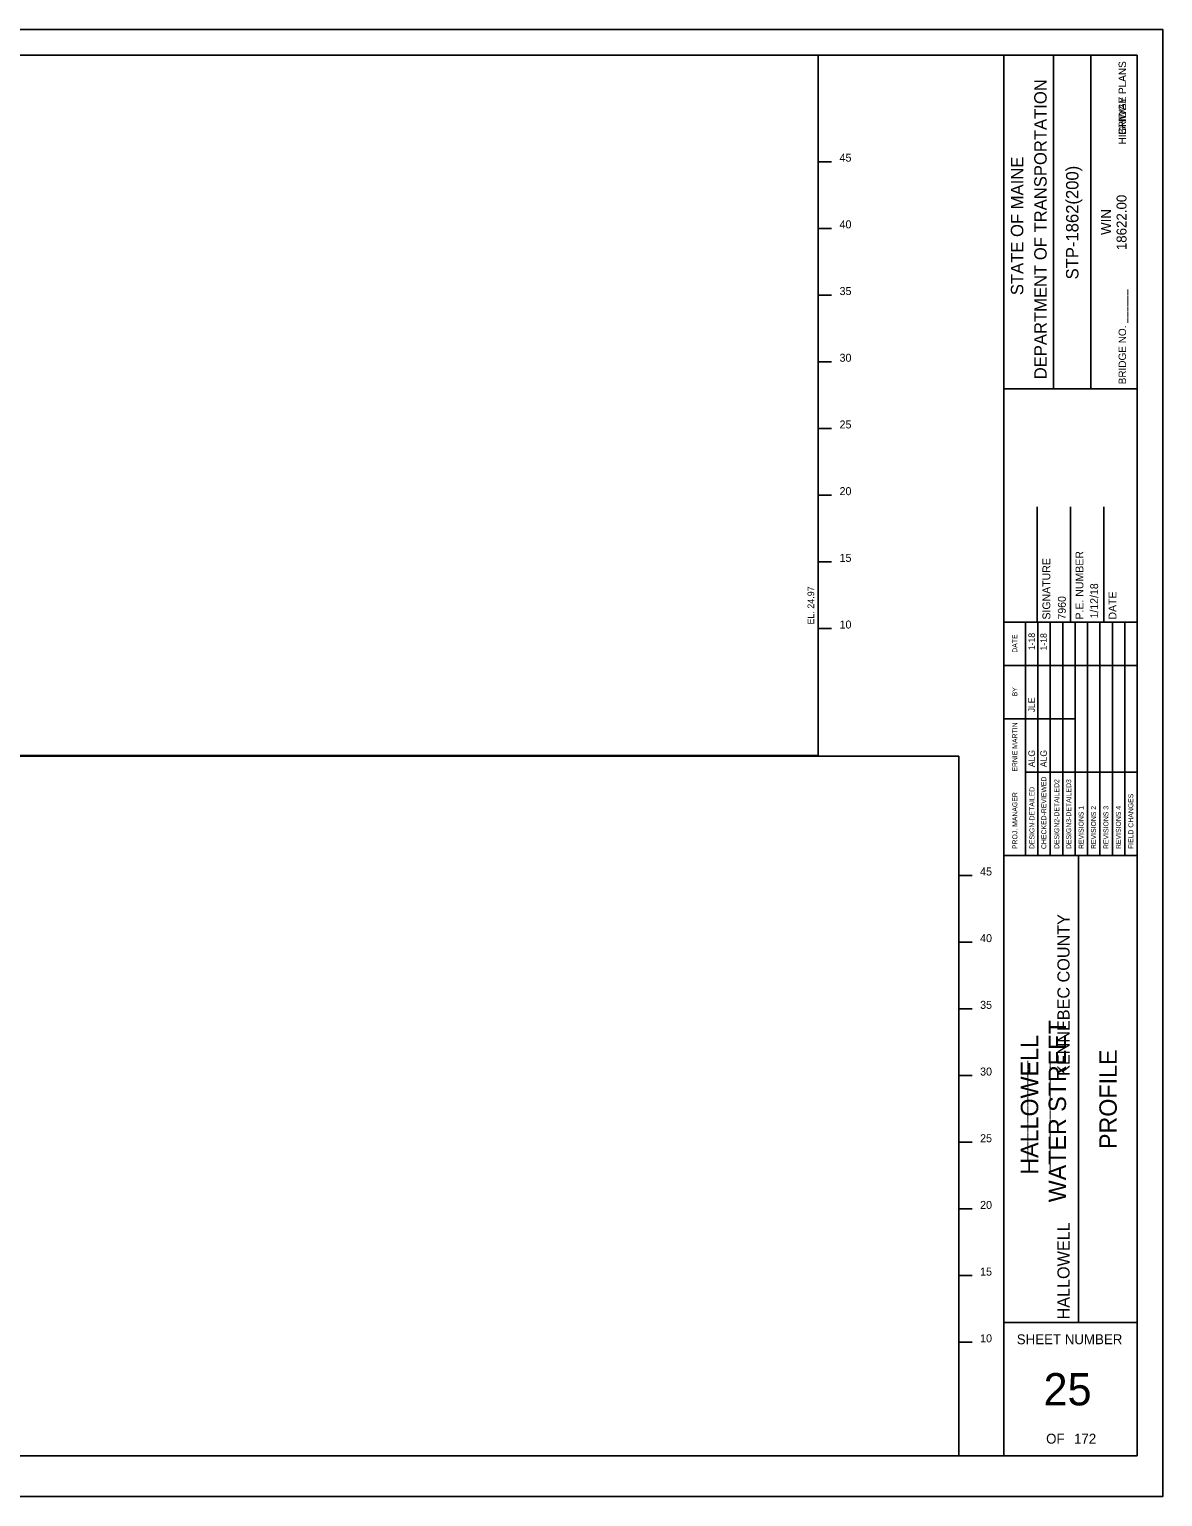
# Model space of a CAD drawing. Extents: x 0 to 850, y 0 to 550.
# Drawn here: x 425 to 850, y 0 to 550 of the extents above; entities that cross this region are included whole.
import ezdxf

# ---------------------------------------------------------------- set-up
doc = ezdxf.new("R2010")
doc.units = 0
for name, color, linetype in [('ANNOTATION', 7, 'Continuous'), ('BORDER', 7, 'Continuous'), ('BRIDGE_TITLE', 7, 'Continuous'), ('Default', 7, 'Continuous'), ('H_V ANNOTATION', 7, 'Continuous'), ('HIGHWAY_TITLE', 7, 'Continuous'), ('MAJOR', 7, 'Continuous'), ('MINOR', 7, 'Continuous'), ('PLOT BOUNDARY', 7, 'Continuous')]:
    doc.layers.add(name, color=color, linetype=linetype)

msp = doc.modelspace()

# ---------------------------------------------------------------- linework, layer by layer
at = {"layer": 'BORDER'}
for p, q in [((840.5, 540.32), (40.47, 540.32)), ((790.49, 15.32), (790.49, 540.33)), ((809.14, 415.3), (809.14, 540.3)), ((823.11, 415.3), (823.11, 540.3)), ((840.5, 15.32), (840.5, 540.32)), ((790.5, 415.29), (840.5, 415.29)), ((802.99, 327.83), (802.99, 371.07)), ((815.5, 327.83), (815.5, 371.07)), ((828, 327.83), (828, 371.07)), ((790.49, 327.83), (840.5, 327.83)), ((790.49, 240.33), (840.5, 240.33)), ((818.45, 65.32), (818.45, 240.33)), ((790.49, 65.32), (840.5, 65.32)), ((40.47, 15.3), (840.5, 15.3))]:
    msp.add_line(p, q, dxfattribs=at)
for points in [[(798.57, 311.58), (798.57, 327.83)], [(803.23, 240.34), (803.23, 327.83)], [(807.89, 327.83), (807.89, 240.34)], [(812.55, 240.34), (812.55, 327.83)], [(817.21, 240.34), (817.21, 327.83)], [(821.87, 240.34), (821.87, 327.83)], [(826.52, 240.34), (826.52, 327.83)], [(831.18, 240.34), (831.18, 327.83)], [(835.84, 240.34), (835.84, 327.83)], [(798.57, 240.34), (798.57, 324.3)], [(790.49, 311.58), (840.5, 311.58)], [(790.49, 291.58), (798.57, 291.58)], [(798.57, 291.58), (817.2, 291.58)], [(798.57, 271.58), (840.5, 271.58)]]:
    msp.add_lwpolyline(points, dxfattribs=at)
at = {"layer": 'Default'}
for points in [[(40.47, 540.32), (720.84, 540.32), (720.84, 277.81), (40.47, 277.81)], [(773.55, 277.59), (73.55, 277.59), (73.55, 15.3), (773.55, 15.3)]]:
    msp.add_lwpolyline(points, close=True, dxfattribs=at)
at = {"layer": 'MAJOR'}
for p, q in [((725.86, 500.42), (720.86, 500.42)), ((725.86, 500.42), (720.86, 500.42)), ((725.86, 475.42), (720.86, 475.42)), ((725.86, 450.42), (720.86, 450.42)), ((725.86, 425.42), (720.86, 425.42)), ((725.86, 400.42), (720.86, 400.42)), ((725.86, 375.42), (720.86, 375.42)), ((725.86, 350.42), (720.86, 350.42)), ((725.86, 325.42), (720.86, 325.42)), ((720.86, 320.42), (720.86, 325.42)), ((778.57, 232.86), (773.57, 232.86)), ((778.57, 232.86), (773.57, 232.86)), ((778.57, 207.86), (773.57, 207.86)), ((778.57, 182.86), (773.57, 182.86)), ((778.57, 157.86), (773.57, 157.86)), ((778.57, 132.86), (773.57, 132.86)), ((778.57, 107.86), (773.57, 107.86)), ((778.57, 82.86), (773.57, 82.86)), ((778.57, 57.86), (773.57, 57.86)), ((773.57, 52.86), (773.57, 57.86))]:
    msp.add_line(p, q, dxfattribs=at)
at = {"layer": 'MINOR'}
msp.add_line((720.84, 325.42), (720.84, 500.42), dxfattribs=at)
at = {"layer": 'PLOT BOUNDARY'}
msp.add_lwpolyline([(0, 0.01), (850.03, 0.01), (850.03, 550.02), (0, 550.02)], close=True, dxfattribs=at)

# ---------------------------------------------------------------- texts
at = {"layer": 'ANNOTATION'}
msp.add_text('EL. 24.97', height=2.5, rotation=90, dxfattribs=at).set_placement((719.34, 326.92))
at = {"layer": 'BORDER'}
for s, height, p in [('DEPARTMENT OF TRANSPORTATION', 4.6589, (806.53, 418.85)), ('STATE OF MAINE', 4.6589, (797.77, 450.38)), ('STP-1862(200)', 4.6589, (818.45, 456.29)), ('18622.00', 3.726, (836.47, 467.25)), ('WIN', 3.726, (830.68, 472.97)), ('P.E. NUMBER', 2.9528, (820.3, 328.79)), ('SIGNATURE', 2.953, (807.9, 328.79)), ('1/12/18', 2.953, (825.82, 329.19)), ('7960', 2.953, (813.7, 328.79)), ('DATE', 2.953, (832.7, 328.79)), ('DATE', 1.857, (795.52, 316.36)), ('1-18', 2.423, (802.11, 317.32)), ('1-18', 2.423, (806.58, 317.2)), ('BY', 1.857, (795.52, 300)), ('JLE', 2.423, (802.11, 294)), ('ERNIE MARTIN', 1.8638, (795.52, 271.78)), ('ALG', 2.423, (802.11, 273.44)), ('ALG', 2.423, (806.58, 273.44)), ('DESIGN-DETAILED', 1.8638, (801.93, 242.77)), ('CHECKED-REVIEWED', 1.8638, (806.4, 242.77)), ('DESIGN2-DETAILED2', 1.8638, (811.24, 242.77)), ('DESIGN3-DETAILED3', 1.8638, (815.72, 242.77)), ('PROJ. MANAGER', 1.8638, (795.52, 242.77)), ('FIELD CHANGES', 1.8638, (839.01, 242.77)), ('REVISIONS 1', 1.8638, (820.38, 242.77)), ('REVISIONS 2', 1.8638, (825.03, 242.77)), ('REVISIONS 3', 1.8638, (829.69, 242.77)), ('REVISIONS 4', 1.8638, (834.35, 242.77)), ('PROFILE', 6.522, (832.82, 130.31))]:
    msp.add_text(s, height=height, rotation=90, dxfattribs=at).set_placement(p)
for s, height, p in [('SHEET NUMBER', 3.7265, (795.32, 57.14)), ('25', 12.097, (805.37, 34.22)), ('OF', 3.726, (806.33, 19.87)), ('172', 3.726, (816.78, 19.87))]:
    msp.add_text(s, height=height, dxfattribs=at).set_placement(p)
at = {"layer": 'BRIDGE_TITLE'}
for s, height, p in [('BRIDGE PLANS', 2.7951, (836.29, 510.44)), ('BRIDGE NO. ______', 2.7951, (836.29, 416.97)), ('KENNEBEC COUNTY', 4.5359, (815.1, 157.71)), ('_____________', 4.5359, (806.71, 121.26)), ('___________', 4.5359, (798.33, 126.24)), ('HALLOWELL', 4.536, (815.1, 66.43))]:
    msp.add_text(s, height=height, rotation=90, dxfattribs=at).set_placement(p)
at = {"layer": 'H_V ANNOTATION'}
for s, p in [('45', (728.86, 500.42)), ('45', (728.86, 500.42)), ('40', (728.86, 475.42)), ('35', (728.86, 450.42)), ('30', (728.86, 425.42)), ('25', (728.86, 400.42)), ('20', (728.86, 375.42)), ('15', (728.86, 350.42)), ('10', (728.86, 325.42)), ('45', (781.57, 232.86)), ('45', (781.57, 232.86)), ('40', (781.57, 207.86)), ('35', (781.57, 182.86)), ('30', (781.57, 157.86)), ('25', (781.57, 132.86)), ('20', (781.57, 107.86)), ('15', (781.57, 82.86)), ('10', (781.57, 57.86))]:
    msp.add_text(s, height=3, dxfattribs=at).set_placement(p)
at = {"layer": 'HIGHWAY_TITLE'}
for s, height, p in [('HIGHWAY PLANS', 2.7951, (836.29, 506.89)), ('WATER STREET', 6.5216, (813.79, 110.36)), ('HALLOWELL', 6.522, (803.36, 120.69))]:
    msp.add_text(s, height=height, rotation=90, dxfattribs=at).set_placement(p)

doc.saveas('drawing.dxf')
